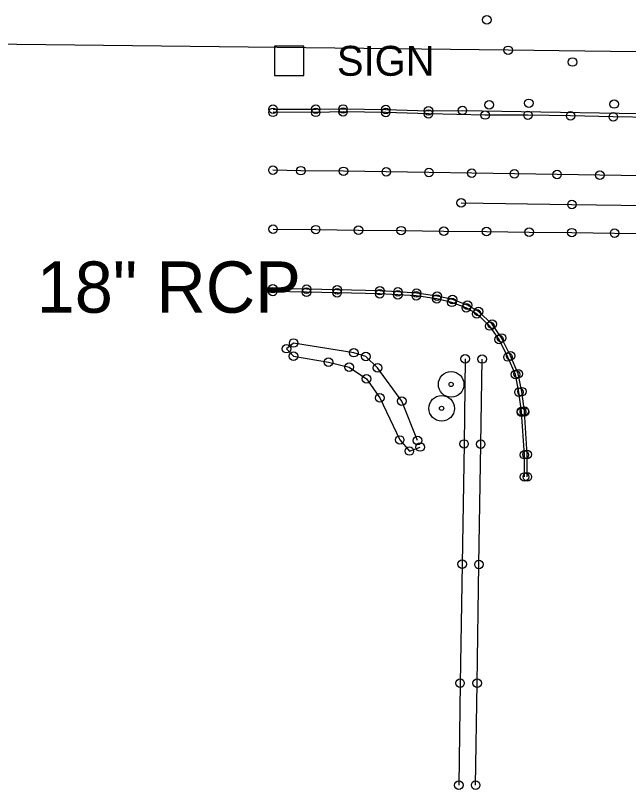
# Model space of a CAD drawing. Extents: x 20503438 to 20508873, y 7964251 to 7984667.
# Drawn here: x 20504667.5 to 20504811.1, y 7970426 to 7970607.2 of the extents above; entities that cross this region are included whole.
import ezdxf

# ---------------------------------------------------------------- set-up
doc = ezdxf.new("R2010")
doc.units = 0
for name, color, linetype in [('SurBreakLine', 7, 'Continuous'), ('SurConcreteSlab', 7, 'Continuous'), ('SurEdgeCurb', 7, 'Continuous'), ('SurEdgeRoadPaved', 7, 'Continuous'), ('SurEdgeSidewalk', 7, 'Continuous'), ('SurFenceWire', 7, 'Continuous'), ('SurHedge', 7, 'Continuous'), ('SurPointsNonDTM', 7, 'Continuous'), ('SurRoadPoints', 7, 'Continuous'), ('SurSurveyPoints', 7, 'Continuous'), ('SurTxtDrainage', 7, 'Continuous')]:
    doc.layers.add(name, color=color, linetype=linetype)

msp = doc.modelspace()

# ---------------------------------------------------------------- linework, layer by layer
at = {"layer": 'SurBreakLine'}
msp.add_lwpolyline([(20504771.9, 7970563.37), (20504797.86, 7970563), (20504843.99, 7970562.34), (20504867.04, 7970562.01), (20505027.11, 7970559.46), (20505056.57, 7970559.02), (20505122.33, 7970557.99), (20505134.3, 7970557.78), (20505181.34, 7970557.02), (20505190.04, 7970556.88), (20505298.19, 7970555.19), (20505381.79, 7970553.77), (20505481.65, 7970551.95), (20505538.21, 7970551.74), (20505602.69, 7970550.28), (20505659.98, 7970549.19), (20505725.91, 7970548.38)], dxfattribs=at)
at = {"layer": 'SurConcreteSlab'}
for points in [[(20504814.37, 7970569.72), (20504804.37, 7970569.87), (20504794.37, 7970570.01), (20504784.37, 7970570.16), (20504774.38, 7970570.31), (20504764.38, 7970570.46), (20504754.38, 7970570.61), (20504744.38, 7970570.76), (20504734.38, 7970570.9), (20504727.84, 7970571)], [(20504727.86, 7970557.22), (20504737.85, 7970557.1), (20504747.85, 7970556.98), (20504757.85, 7970556.87), (20504767.85, 7970556.75), (20504777.85, 7970556.64), (20504787.85, 7970556.52), (20504797.85, 7970556.4), (20504807.85, 7970556.29), (20504817.85, 7970556.17)]]:
    msp.add_lwpolyline(points, dxfattribs=at)
at = {"layer": 'SurEdgeCurb'}
for points in [[(20504892.42, 7970582.21), (20504891.81, 7970582.22), (20504887.15, 7970582.36), (20504884.51, 7970582.49), (20504883.4, 7970582.67), (20504875.45, 7970582.95), (20504874.56, 7970582.74), (20504866.97, 7970582.51), (20504864.69, 7970582.59), (20504854.69, 7970582.84), (20504846.61, 7970583.02), (20504836.61, 7970583.12), (20504826.61, 7970583.3), (20504816.61, 7970583.36), (20504807.55, 7970583.5), (20504797.55, 7970583.74), (20504787.56, 7970583.87), (20504777.56, 7970583.93), (20504764.24, 7970584.18), (20504754.24, 7970584.51), (20504744.25, 7970584.65), (20504737.85, 7970584.55), (20504727.85, 7970584.56)], [(20504786.75, 7970499.2), (20504786.72, 7970504.41), (20504786.06, 7970514.37), (20504786.04, 7970514.51), (20504785.45, 7970519.04), (20504784.62, 7970523.17), (20504782.88, 7970527.27), (20504780.79, 7970531.36), (20504778.64, 7970534.53), (20504775.55, 7970537.39), (20504773.12, 7970538.8), (20504769.74, 7970540.07), (20504766.19, 7970540.87), (20504761.41, 7970541.58), (20504757.08, 7970541.86), (20504752.84, 7970542.09), (20504742.85, 7970542.32), (20504735.71, 7970542.47), (20504727.78, 7970542.59)], [(20504787.41, 7970499.22), (20504787.39, 7970504.45), (20504786.74, 7970514.42), (20504786.72, 7970514.58), (20504786.15, 7970519.17), (20504785.28, 7970523.37), (20504783.5, 7970527.56), (20504781.38, 7970531.74), (20504779.16, 7970534.98), (20504775.97, 7970537.93), (20504773.42, 7970539.41), (20504769.91, 7970540.73), (20504766.3, 7970541.53), (20504761.48, 7970542.26), (20504757.11, 7970542.54), (20504752.86, 7970542.8), (20504742.87, 7970542.99), (20504735.72, 7970543.18), (20504727.79, 7970543.27)]]:
    msp.add_lwpolyline(points, dxfattribs=at)
at = {"layer": 'SurEdgeRoadPaved'}
msp.add_lwpolyline([(20504727.85, 7970585.32), (20504737.85, 7970585.29), (20504744.25, 7970585.34), (20504754.25, 7970585.2), (20504764.26, 7970584.93), (20504772.2, 7970585.02), (20504827.27, 7970584.09), (20504841.35, 7970583.88), (20504874.77, 7970583.4)], dxfattribs=at)
at = {"layer": 'SurEdgeSidewalk'}
for points in [[(20504772.83, 7970526.84), (20504772.59, 7970506.93), (20504772.16, 7970478.78), (20504771.65, 7970450.91), (20504771.36, 7970427.03)], [(20504775.31, 7970427.03), (20504775.67, 7970450.92), (20504776.08, 7970478.72), (20504776.49, 7970506.89), (20504776.82, 7970526.81)]]:
    msp.add_lwpolyline(points, dxfattribs=at)
at = {"layer": 'SurFenceWire'}
msp.add_lwpolyline([(20504884.71, 7970597.81), (20504782.91, 7970599.08), (20504566.31, 7970601.59), (20504471.49, 7970602.55)], dxfattribs=at)
at = {"layer": 'SurHedge'}
msp.add_lwpolyline([(20504761.71, 7970507.73), (20504758.01, 7970516.96), (20504752.31, 7970524.73), (20504749.58, 7970527.38), (20504746.79, 7970528.29), (20504732.68, 7970530.56), (20504731.01, 7970529.22), (20504732.63, 7970527.47), (20504740.86, 7970526.09), (20504745.68, 7970524.9), (20504749.75, 7970522.15), (20504752.86, 7970517.73), (20504757.52, 7970507.86), (20504759.79, 7970505.27), (20504762.3, 7970506.21)], dxfattribs=at)
at = {"layer": 'SurPointsNonDTM'}
for centre in [(20504782.91, 7970599.08), (20504732.68, 7970530.56), (20504731.01, 7970529.22), (20504746.79, 7970528.29), (20504732.63, 7970527.47), (20504749.58, 7970527.38), (20504740.86, 7970526.09), (20504745.68, 7970524.9), (20504752.31, 7970524.73), (20504749.75, 7970522.15), (20504752.86, 7970517.73), (20504758.01, 7970516.96), (20504757.52, 7970507.86), (20504761.71, 7970507.73), (20504759.79, 7970505.27), (20504762.3, 7970506.21)]:
    msp.add_circle(centre, 1, dxfattribs=at)
at = {"layer": 'SurRoadPoints'}
msp.add_lwpolyline([(20504731.61, 7970593.19), (20504731.61, 7970593.19), (20504735.04, 7970593.19), (20504735.04, 7970600.05), (20504728.18, 7970600.05), (20504728.18, 7970593.19), (20504731.61, 7970593.19)], dxfattribs=at)
for centre, radius in [((20504769.57, 7970520.87), 3), ((20504769.57, 7970520.87), 0.5), ((20504767.34, 7970515.26), 3), ((20504767.34, 7970515.26), 0.5)]:
    msp.add_circle(centre, radius, dxfattribs=at)
at = {"layer": 'SurSurveyPoints'}
for centre in [(20504777.93, 7970606.23), (20504797.98, 7970596.34), (20504778.49, 7970586.32), (20504787.77, 7970586.68), (20504807.77, 7970586.5), (20504727.85, 7970585.32), (20504727.85, 7970584.56), (20504737.85, 7970585.29), (20504737.85, 7970584.55), (20504744.25, 7970585.34), (20504744.25, 7970584.65), (20504754.24, 7970584.51), (20504754.25, 7970585.2), (20504764.26, 7970584.93), (20504772.2, 7970585.02), (20504764.24, 7970584.18), (20504777.56, 7970583.93), (20504787.56, 7970583.87), (20504797.55, 7970583.74), (20504807.55, 7970583.5), (20504727.84, 7970571), (20504734.38, 7970570.9), (20504744.38, 7970570.76), (20504754.38, 7970570.61), (20504764.38, 7970570.46), (20504774.38, 7970570.31), (20504784.37, 7970570.16), (20504794.37, 7970570.01), (20504804.37, 7970569.87), (20504771.9, 7970563.37), (20504797.86, 7970563), (20504727.86, 7970557.22), (20504737.85, 7970557.1), (20504747.85, 7970556.98), (20504757.85, 7970556.87), (20504767.85, 7970556.75), (20504777.85, 7970556.64), (20504787.85, 7970556.52), (20504797.85, 7970556.4), (20504807.85, 7970556.29), (20504727.79, 7970543.27), (20504735.72, 7970543.18), (20504742.87, 7970542.99), (20504752.86, 7970542.8), (20504727.78, 7970542.59), (20504735.71, 7970542.47), (20504742.85, 7970542.32), (20504752.84, 7970542.09), (20504757.08, 7970541.86), (20504757.11, 7970542.54), (20504761.41, 7970541.58), (20504761.48, 7970542.26), (20504766.3, 7970541.53), (20504766.19, 7970540.87), (20504769.74, 7970540.07), (20504769.91, 7970540.73), (20504773.42, 7970539.41), (20504773.12, 7970538.8), (20504775.55, 7970537.39), (20504775.97, 7970537.93), (20504778.64, 7970534.53), (20504779.16, 7970534.98), (20504780.79, 7970531.36), (20504781.38, 7970531.74), (20504772.83, 7970526.84), (20504776.82, 7970526.81), (20504782.88, 7970527.27), (20504783.5, 7970527.56), (20504784.62, 7970523.17), (20504785.28, 7970523.37), (20504786.15, 7970519.17), (20504785.45, 7970519.04), (20504786.04, 7970514.51), (20504786.06, 7970514.37), (20504786.72, 7970514.58), (20504786.74, 7970514.42), (20504772.59, 7970506.93), (20504776.49, 7970506.89), (20504786.72, 7970504.41), (20504787.39, 7970504.45), (20504786.75, 7970499.2), (20504787.41, 7970499.22), (20504772.16, 7970478.78), (20504776.08, 7970478.72), (20504771.65, 7970450.91), (20504775.67, 7970450.92), (20504771.36, 7970427.03), (20504775.31, 7970427.03)]:
    msp.add_circle(centre, 1, dxfattribs=at)

# ---------------------------------------------------------------- texts
at = {"layer": 'SurRoadPoints'}
msp.add_text('SIGN', height=6.995, rotation=360, dxfattribs=at).set_placement((20504742.82, 7970593.12))
at = {"layer": 'SurTxtDrainage'}
msp.add_text('18" RCP', height=12, dxfattribs=at).set_placement((20504672.5, 7970537.65))

doc.saveas('drawing.dxf')
